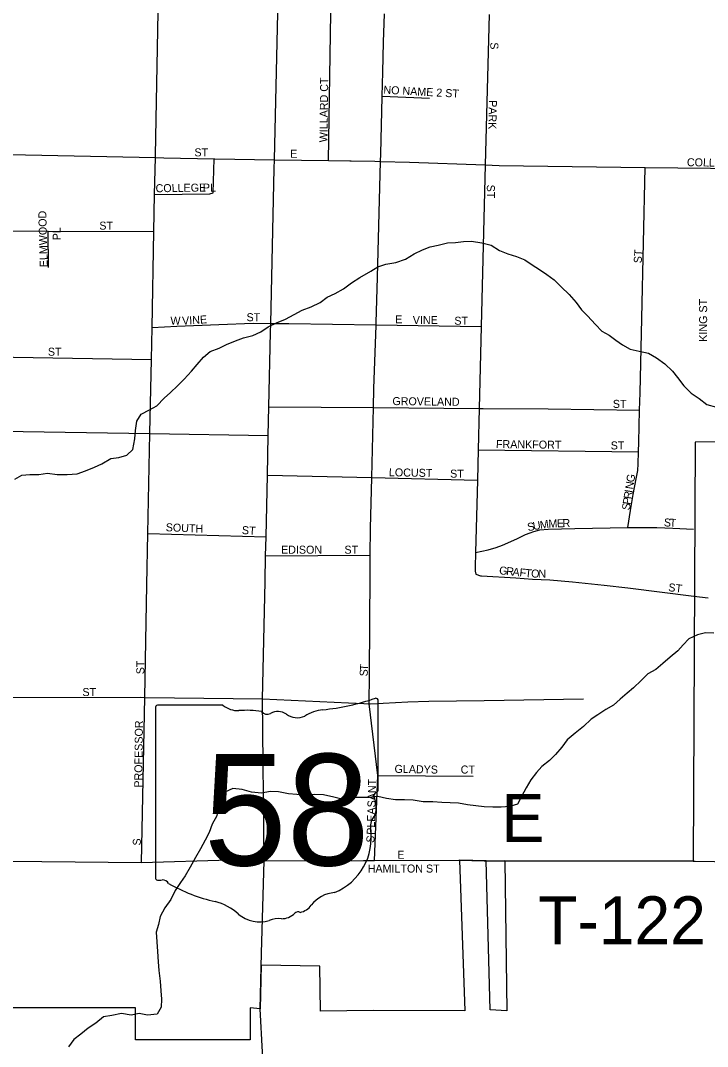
# Model space of a CAD drawing. Extents: x 1857828 to 2277390, y 930619 to 1324581.
# Drawn here: x 2044604 to 2048895, y 1193698 to 1200105 of the extents above; entities that cross this region are included whole.
import ezdxf

# ---------------------------------------------------------------- set-up
doc = ezdxf.new("R2010")
doc.units = 0
for name, color, linetype in [('GM_X_City_Street', 7, 'Continuous'), ('GM_X_City_Street_Text', 7, 'Continuous'), ('GM_X_Corporation', 7, 'Continuous'), ('GM_X_Minor_River', 7, 'Continuous'), ('GM_X_State_Location', 7, 'Continuous'), ('GM_X_State_Route', 7, 'Continuous'), ('GM_X_State_Shield', 7, 'Continuous'), ('GM_X_Township_Road', 7, 'Continuous'), ('GM_X_Township_Road_Text', 7, 'Continuous')]:
    doc.layers.add(name, color=color, linetype=linetype)

msp = doc.modelspace()

# ---------------------------------------------------------------- linework, layer by layer
at = {"layer": 'GM_X_City_Street'}
for points in [[(2045446.7, 1199263.6), (2045446.7, 1199263.6), (2045464.4, 1200157.6)], [(2046526.9, 1199230.2), (2046541.5, 1200150.6)], [(2046670.4, 1199228.3), (2046817, 1199226.3), (2046852.7, 1199225.3), (2047032.9, 1199220), (2047507, 1199203.7), (2047594.5, 1199200.7), (2048506.7, 1199187.8), (2048914.4, 1199183.5), (2049785.3, 1199177.2), (2050061.2, 1199175.5), (2050800.9, 1199205), (2050967.2, 1199208.4), (2051658.7, 1199196.2), (2051734, 1199217.2), (2052172.9, 1199504.5), (2052500.1, 1199734.7), (2053014.1, 1200096.5)], [(2046825.8, 1198209.1), (2046826.1, 1198216.6), (2046833.9, 1198503.3), (2046852.7, 1199225.3), (2046853.9, 1199273.1), (2046863.2, 1199628), (2046863.3, 1199632.7), (2046868, 1199782.4), (2046870.5, 1199970.8), (2046877.1, 1200147.7)], [(2047530.5, 1200142.3), (2047507, 1199203.7), (2047481.6, 1198193.5), (2047468.8, 1197682.7), (2047462.3, 1197423.5), (2047457.6, 1197235.2), (2047446.3, 1196783.5), (2047444, 1196692), (2047444.2, 1196666), (2047448.3, 1196648), (2047476.4, 1196638.2), (2047482.6, 1196637.8)], [(2046863.3, 1199632.7), (2047158.9, 1199620.1)], [(2044124.8, 1199276.8), (2045446.5, 1199249.9), (2045499.1, 1199248.8), (2045499.3, 1199248.8)], [(2045412.5, 1197528.1), (2045421.6, 1197989.2), (2045425.5, 1198188.6), (2045437.3, 1198787.4), (2045441.9, 1199018.2), (2045446.5, 1199249.9), (2045446.7, 1199263.6)], [(2045441.9, 1199018.2), (2045787.1, 1199022.8), (2045807, 1199029), (2045813, 1199242.4)], [(2045499.3, 1199248.8), (2045813, 1199242.4), (2045818.3, 1199242.3)], [(2045818.3, 1199242.3), (2046190.4, 1199234.7)], [(2046190.4, 1199234.7), (2046526.9, 1199230.2), (2046660.4, 1199228.4), (2046670.4, 1199228.3)], [(2048484.6, 1198244.1), (2048484.6, 1198245.5), (2048506.7, 1199187.8)], [(2043167.1, 1198799.5), (2043167.2, 1198799.5), (2043177.6, 1198799.3), (2044088.7, 1198791.9), (2044114.9, 1198791.9), (2044332.4, 1198791.7), (2044776.1, 1198790), (2045437.3, 1198787.4)], [(2044779.7, 1198562.5), (2044776.1, 1198790)], [(2048398.3, 1196938.6), (2048413.4, 1197045.5), (2048430.6, 1197145.8), (2048449.8, 1197242.2), (2048459.4, 1197294.4), (2048463.1, 1197336.5), (2048464.7, 1197412.6), (2048466, 1197472.8), (2048471, 1197671.2), (2048473.7, 1197779.6), (2048484.6, 1198244.1)], [(2045425.5, 1198188.6), (2045580.9, 1198195.9), (2045842.6, 1198206.1), (2046058.3, 1198215.9), (2046167.6, 1198212.3)], [(2046167.6, 1198212.3), (2046280.1, 1198213.7), (2046825.7, 1198204.5), (2047481.6, 1198193.5)], [(2046816.1, 1194858.7), (2046835.2, 1195391.2), (2046781.4, 1195837.6), (2046783, 1196021.3), (2046788.2, 1196648.8), (2046789, 1196767), (2046790, 1196933.4), (2046797.7, 1197250.6), (2046808.4, 1197688.1), (2046811.3, 1197807.5), (2046825.5, 1198200.8), (2046825.7, 1198204.5), (2046825.8, 1198209.1)], [(2043111.3, 1198029.2), (2044068.7, 1198012), (2044098.6, 1198011.5), (2044146.6, 1198010.6), (2044560.2, 1198003.6), (2045421.6, 1197989.2)], [(2046156, 1197693.4), (2046808.4, 1197688.1), (2047468.8, 1197682.7), (2047492.9, 1197682.5), (2047493.6, 1197682.5)], [(2047493.6, 1197682.5), (2047899.1, 1197679.2), (2048471, 1197671.2)], [(2043118.3, 1197563), (2044089.8, 1197547.3), (2045412.4, 1197526), (2046152, 1197514.1)], [(2045393.7, 1196581.5), (2045400, 1196901), (2045412.4, 1197526), (2045412.5, 1197528.1)], [(2047462.3, 1197423.5), (2048464.7, 1197412.6)], [(2046146.5, 1197265.7), (2046797.7, 1197250.6), (2047457.6, 1197235.2)], [(2045400, 1196901), (2046137.9, 1196880.3)], [(2047446.3, 1196783.5), (2047526.2, 1196800.5), (2047576.1, 1196814.9), (2047613.9, 1196829.2), (2047703.5, 1196867.9), (2047759.3, 1196896.4), (2047787.1, 1196906.6), (2047811, 1196914.8), (2047848.9, 1196925.1), (2047900.8, 1196929.5), (2048066.6, 1196932.7), (2048398.3, 1196938.6), (2048446.1, 1196939.5), (2048578, 1196938.4), (2048677.9, 1196935.2), (2048807.8, 1196928.1)], [(2046135.2, 1196762.1), (2046789, 1196767)], [(2047482.6, 1196637.8), (2047698.3, 1196624), (2047802.3, 1196616.8), (2047910.2, 1196611.7), (2048052.2, 1196598.9), (2048250.2, 1196578.4), (2048398.2, 1196561.6), (2048810.8, 1196511.1), (2048899.6, 1196500)], [(2045359.4, 1194846.1), (2045379.8, 1195878.3), (2045393.7, 1196581.5), (2045393.7, 1196581.5)], [(2042662.4, 1194873.5), (2042664.6, 1195109.3), (2042671.2, 1195279.7), (2042676.5, 1195380), (2042684.2, 1195410.1), (2042696, 1195434.3), (2042721.9, 1195454.5), (2042763.7, 1195468.8), (2043876.1, 1195779.6), (2044093.4, 1195839.3), (2044145.3, 1195853.7), (2044189.1, 1195864.1), (2044247, 1195872.5), (2044300.9, 1195876.9), (2044356.8, 1195877.3), (2044490.7, 1195878.3), (2045355.7, 1195878.6), (2045379.4, 1195878.3)], [(2045379.4, 1195878.3), (2045379.8, 1195878.3), (2045381.9, 1195878.3), (2046115.3, 1195869.5)], [(2046115.3, 1195869.5), (2046652.6, 1195844), (2046748.5, 1195840.7), (2046781.4, 1195837.6), (2046788.5, 1195836.9), (2046834.5, 1195839.5), (2046834.8, 1195839.5)], [(2046834.8, 1195839.5), (2046870.3, 1195841.5), (2047024.1, 1195850.7), (2047153.9, 1195853.6), (2047499.5, 1195858.2), (2048120.7, 1195868.7)], [(2046835.2, 1195391.2), (2047431.2, 1195386.6)], [(2041697.8, 1194883.4), (2041706.6, 1194883.3), (2042662.4, 1194873.5), (2045359.4, 1194846.1), (2045912.2, 1194863.5), (2046030.1, 1194860), (2046066.8, 1194858.9)], [(2046066.8, 1194858.9), (2046125.8, 1194857.1)], [(2046125.8, 1194857.1), (2046747.5, 1194858.6), (2046792.2, 1194858.7), (2046816.1, 1194858.7), (2047342.9, 1194862.3)], [(2047500.9, 1194857.9), (2047513.1, 1194857.5), (2047606.2, 1194856.7)]]:
    msp.add_lwpolyline(points, dxfattribs=at)
at = {"layer": 'GM_X_Corporation'}
msp.add_lwpolyline([(2051694.1, 1197494.8), (2048818.4, 1197472.4), (2048806.7, 1194856.2), (2047629.8, 1194856.4), (2047642.2, 1193919.8), (2047537.4, 1193926.2), (2047513.1, 1194857.5), (2047346, 1194862.3), (2047379.1, 1193919.8), (2046807.5, 1193921.8), (2046477.5, 1193918.9), (2046474.2, 1194200.3), (2046107.4, 1194206.5), (2046100.3, 1193934.1), (2046037.6, 1193939.9), (2046037.6, 1193739.8), (2045321.5, 1193739.9), (2045321.5, 1193940), (2042130.6, 1193940.3), (2042130.5, 1193127.5)], dxfattribs=at)
at = {"layer": 'GM_X_Minor_River'}
for points in [[(2046835.8, 1198566.9), (2046885.8, 1198583), (2046947.7, 1198593.1), (2047009.7, 1198615.3), (2047063.6, 1198647.4), (2047115.6, 1198673.6), (2047163.5, 1198691.7), (2047213.5, 1198701.8), (2047271.5, 1198715.9), (2047321.5, 1198718), (2047371.5, 1198726.1), (2047421.5, 1198728.1), (2047485.5, 1198716.2), (2047543.6, 1198702.2), (2047595.6, 1198668.2), (2047647.7, 1198648.3), (2047701.7, 1198632.3), (2047753.8, 1198610.3), (2047799.9, 1198580.3), (2047845.9, 1198550.3), (2047892, 1198518.3), (2047938.1, 1198486.3), (2047982.2, 1198442.3), (2048030.3, 1198394.2), (2048074.4, 1198344.2), (2048108.6, 1198298.1), (2048146.7, 1198260.1), (2048194.8, 1198206), (2048234.9, 1198166), (2048280.9, 1198140), (2048323, 1198109.9), (2048365.1, 1198079.9), (2048413.2, 1198051.9), (2048469.2, 1198040), (2048527.2, 1198028.1), (2048577.3, 1197998), (2048629.4, 1197962), (2048677.5, 1197916), (2048707.6, 1197875.9), (2048747.7, 1197823.9), (2048793.8, 1197777.8), (2048843.9, 1197743.8), (2048892, 1197707.8), (2048952.1, 1197689.8)], [(2044568.7, 1197240.5), (2044612.6, 1197266.7), (2044662.6, 1197270.7), (2044718.6, 1197270.8), (2044772.6, 1197278.9), (2044832.6, 1197271), (2044894.6, 1197269.1), (2044958.6, 1197275.2), (2045010.6, 1197293.3), (2045066.5, 1197315.4), (2045112.5, 1197337.5), (2045168.4, 1197369.7), (2045218.4, 1197375.8), (2045268.4, 1197389.9), (2045306.3, 1197426), (2045318.2, 1197492.2), (2045322, 1197544.3), (2045329.9, 1197602.5), (2045357.8, 1197646.6), (2045409.7, 1197674.8), (2045455.7, 1197698.9), (2045501.6, 1197747.1), (2045541.5, 1197783.2), (2045585.4, 1197823.4), (2045627.3, 1197865.5), (2045671.2, 1197915.7), (2045707.1, 1197957.9), (2045747, 1198002), (2045788.9, 1198038.2), (2045844.9, 1198058.3), (2045890.8, 1198082.4), (2045946.8, 1198104.6), (2045996.8, 1198122.7), (2046054.7, 1198138.8), (2046104.7, 1198160.9), (2046150.6, 1198193.1), (2046202.6, 1198217.2), (2046258.5, 1198239.3), (2046314.4, 1198269.5), (2046364.4, 1198295.6), (2046420.3, 1198317.7), (2046476.3, 1198343.9), (2046520.2, 1198378), (2046570.2, 1198400.1), (2046622.1, 1198430.3), (2046672, 1198466.4), (2046723.9, 1198500.6), (2046791.9, 1198540.8), (2046835.8, 1198566.9)], [(2048935.4, 1196278.5), (2048883.4, 1196280.4), (2048833.4, 1196268.3), (2048779.4, 1196244.2), (2048743.5, 1196206), (2048709.6, 1196167.9), (2048661.7, 1196129.7), (2048615.8, 1196089.6), (2048571.9, 1196051.4), (2048521.9, 1196025.3), (2048482, 1195983.1), (2048434.1, 1195936.9), (2048394.2, 1195904.8), (2048350.3, 1195866.6), (2048308.3, 1195830.5), (2048260.4, 1195802.4), (2048210.5, 1195770.2), (2048168.5, 1195742.1), (2048120.7, 1195695.9), (2048068.7, 1195655.7), (2048018.8, 1195613.6), (2047984.9, 1195567.4), (2047945, 1195521.2), (2047909.1, 1195483.1), (2047861.2, 1195446.9), (2047827.3, 1195408.8), (2047791.4, 1195362.6), (2047763.5, 1195312.5), (2047733.6, 1195258.3), (2047707.7, 1195212.2), (2047659.8, 1195196.1), (2047605.8, 1195192), (2047553.8, 1195191.9), (2047499.8, 1195193.8), (2047447.7, 1195201.8), (2047395.7, 1195207.7), (2047339.7, 1195217.6), (2047287.7, 1195219.6)], [(2047287.7, 1195219.6), (2047235.7, 1195221.5), (2047179.7, 1195225.4), (2047119.6, 1195225.4), (2047057.6, 1195235.3), (2047003.6, 1195239.2), (2046945.6, 1195239.1), (2046889.6, 1195247.1), (2046835.5, 1195259), (2046779.5, 1195252.9), (2046723.5, 1195252.9), (2046669.5, 1195252.8), (2046619.6, 1195240.7), (2046561.5, 1195254.6), (2046497.5, 1195268.6), (2046441.5, 1195272.5), (2046389.5, 1195270.4), (2046329.5, 1195272.3), (2046277.4, 1195276.3), (2046215.4, 1195288.2), (2046163.4, 1195290.1), (2046109.4, 1195280), (2046047.4, 1195286), (2045989.3, 1195303.9), (2045929.3, 1195309.9), (2045879.4, 1195285.7), (2045855.5, 1195241.6), (2045839.6, 1195191.4), (2045829.7, 1195139.3), (2045801.8, 1195087.1), (2045782, 1195035), (2045758.1, 1194986.8), (2045728.2, 1194932.7), (2045696.3, 1194878.5), (2045664.4, 1194818.3), (2045632.6, 1194764.1), (2045602.7, 1194722), (2045570.8, 1194671.8), (2045542.9, 1194615.6), (2045505, 1194563.5), (2045477.1, 1194509.3), (2045465.3, 1194459.2), (2045451.4, 1194411), (2045455.5, 1194350.9), (2045459.7, 1194290.8), (2045463.8, 1194226.6), (2045467.9, 1194172.5), (2045476.1, 1194106.3), (2045480.2, 1194046.2), (2045484.3, 1193994.1), (2045482.5, 1193944), (2045458.6, 1193899.8), (2045396.6, 1193893.7), (2045344.5, 1193903.7), (2045294.6, 1193893.6), (2045234.5, 1193903.5), (2045174.6, 1193891.4), (2045122.6, 1193883.3), (2045074.7, 1193843.1), (2045026.7, 1193813), (2044980.8, 1193774.8), (2044936.9, 1193740.7), (2044903, 1193696.5)]]:
    msp.add_lwpolyline(points, dxfattribs=at)
at = {"layer": 'GM_X_State_Route'}
for points in [[(2046189.2, 1199180.9), (2046190.4, 1199234.7), (2046210.9, 1200153.3)], [(2046166.4, 1198158.6), (2046167.6, 1198212.3), (2046189.2, 1199180.9)], [(2046131.6, 1196599.6), (2046131.7, 1196601.4), (2046135.2, 1196762.1), (2046137.9, 1196880.3), (2046146.5, 1197265.7), (2046152, 1197514.1), (2046156, 1197693.4), (2046166.4, 1198158.6)], [(2046125.8, 1194857.1), (2046115.3, 1195869.5), (2046131.6, 1196599.6)], [(2046109.9, 1194281.7), (2046125.8, 1194857.1)], [(2046224.7, 1192985.3), (2046210.8, 1193045.7), (2046206.9, 1193062.9), (2046130.5, 1193392), (2046100.3, 1193934.1), (2046109.9, 1194281.7)]]:
    msp.add_lwpolyline(points, dxfattribs=at)
at = {"layer": 'GM_X_State_Shield'}
for p, q in [((2045446.6, 1195810.8), (2045446.6, 1194754.2)), ((2045868, 1195829), (2045460.3, 1195829)), ((2046838.7, 1195302.4), (2046838.7, 1195855.2)), ((2046838.6, 1195302.6), (2046838.7, 1195302.4))]:
    msp.add_line(p, q, dxfattribs=at)
for centre, radius, start, end in [((2046342.8, 1197269.5), 1476.4, 275.84447, 288.90645), ((2046823.3, 1195857.5), 15.5, 351.86209, 97.738), ((2045462.5, 1195813.1), 16.1, 98.1301, 188.1301), ((2045965.1, 1195951.7), 156.4, 231.61951, 271.11188), ((2046531.1, 1195506.3), 297, 97.34618, 120.76885), ((2046016.9, 1195235.8), 561.6, 80.48669, 94.98827), ((2046144.4, 1195818.5), 45.1, 219.79206, 297.10237), ((2046210.7, 1195696.4), 93.8, 54.46668, 119.14113), ((2046331.8, 1195863.9), 112.9, 233.85621, 294.82819), ((2046822.2, 1195300.3), 16.6, 289.60381, 7.73413), ((2046835.2, 1195261.9), 24, 107.94398, 210.33697), ((2046682.6, 1195192), 144, 340.03296, 23.64957), ((2046894.3, 1195071.1), 104.8, 136.8065, 186.92959), ((2046425.5, 1195000.8), 369.3, 292.30889, 8.98584), ((2045462.7, 1194751.9), 16.3, 171.95839, 258.30661), ((2045465.1, 1194860), 124.2, 267.33899, 280.60386), ((2045490.5, 1194693.2), 44.8, 29.74838, 93.27175), ((2046055.8, 1195642.6), 1066.1, 240.41292, 257.1985), ((2046581.2, 1194457.5), 202.2, 94.40312, 142.57675), ((2045738, 1194279.5), 333.6, 47.18416, 75.83597), ((2046098.7, 1194688), 211.7, 230.70037, 286.29184), ((2046236.5, 1194608.8), 112.8, 268.77702, 315.54927), ((2046338.5, 1194506.5), 31.8, 65.75173, 132.64842), ((2046325, 1194651.8), 119.3, 282.87319, 323.27711), ((2046221, 1194322.6), 173.9, 85.69512, 111.20995)]:
    msp.add_arc(centre, radius, start, end, dxfattribs=at)
at = {"layer": 'GM_X_Township_Road'}
for points in [[(2047342.9, 1194862.3), (2047345.9, 1194862.3), (2047500.9, 1194857.9)], [(2047606.2, 1194856.7), (2047629.8, 1194856.4), (2048806.7, 1194856.2), (2048818, 1194856)], [(2048818, 1194856), (2052062.8, 1194799.2), (2053528.4, 1194778.3), (2053769.6, 1194772.9)]]:
    msp.add_lwpolyline(points, dxfattribs=at)

# ---------------------------------------------------------------- texts
at = {"layer": 'GM_X_City_Street_Text'}
for s, rotation, p in [('S', 270, (2047538.9, 1199969.2)), ('WILLARD CT', 89.32632, (2046521.3, 1199344.5)), ('NO NAME 2 ST', 356.95682, (2046870.1, 1199648.6)), ('PARK', 268.78171, (2047530.2, 1199608.2)), ('ST', 0.00001, (2045690.3, 1199257)), ('E', 0.00001, (2046288.8, 1199248.2)), ('COLLEGE', 359.21694, (2048766.4, 1199195.4)), ('COLLEGE', 0.90888, (2045448.2, 1199032.6)), ('PL', 0.00001, (2045743.2, 1199037)), ('ST', 270, (2047517, 1199080.4)), ('ELMWOOD', 91.59325, (2044774.5, 1198565.3)), ('PL', 90, (2044855.2, 1198732.8)), ('ST', 0.00001, (2045096.4, 1198799.4)), ('ST', 86.42535, (2048483.8, 1198588.2)), ('KING ST', 90, (2048892.9, 1198099.2)), ('W', 0.00001, (2045540.7, 1198205.4)), ('VINE', 3.46623, (2045615, 1198205.4)), ('ST', 0.00001, (2046016, 1198227.4)), ('E', 0.00001, (2046944.3, 1198214.2)), ('VINE', 0.00001, (2047054.4, 1198209.8)), ('ST', 0.00001, (2047313.9, 1198205.4)), ('ST', 0.00001, (2044775.1, 1198011.8)), ('GROVELAND', 359.33416, (2046926.9, 1197703.8)), ('ST', 0.00001, (2048304, 1197686.2)), ('FRANKFORT', 359.3101, (2047573.7, 1197435.4)), ('ST', 0.00001, (2048290.7, 1197426.6)), ('LOCUST', 358.93969, (2046904.9, 1197259.4)), ('ST', 0.00001, (2047287.5, 1197250.6)), ('N', 81.1142, (2048429.5, 1197175)), ('G', 80.22501, (2048436.2, 1197218.3)), ('R', 81.10059, (2048419.9, 1197114.2)), ('I', 81.09099, (2048426.1, 1197153.3)), ('S', 81.11259, (2048409.1, 1197044.6)), ('P', 81.11259, (2048414.5, 1197079.4)), ('SOUTH', 357.51189, (2045510.4, 1196916.2)), ('S', 10.02381, (2047774.3, 1196916.1)), ('U', 10.03885, (2047808.9, 1196922.2)), ('M', 8.55508, (2047851.9, 1196929.8)), ('M', 2.67866, (2047902.8, 1196937.5)), ('E', 1.77626, (2047955.3, 1196940)), ('R', 1.78682, (2047990.5, 1196941.1)), ('S', 355.84432, (2048621.5, 1196947)), ('T', 357.289, (2048658, 1196944.3)), ('ST', 356.42537, (2045985.7, 1196898.6)), ('EDISON', 0.00001, (2046231.6, 1196775.4)), ('ST', 0.00001, (2046627.6, 1196775.4)), ('G', 354.08936, (2047592.1, 1196647.7)), ('R', 354.08886, (2047635.9, 1196643.2)), ('A', 354.10102, (2047675.3, 1196639.1)), ('F', 354.08824, (2047719.1, 1196634.6)), ('T', 354.34993, (2047754.3, 1196631)), ('O', 358.13503, (2047793, 1196627.3)), ('N', 359.97035, (2047838.7, 1196625.8)), ('ST', 352.8649, (2048648.3, 1196542.1)), ('ST', 90, (2045377.3, 1196022.4)), ('T', 86.08958, (2046773.7, 1196043.5)), ('S', 87.37634, (2046772.1, 1196008.6)), ('ST', 0.00001, (2044990.7, 1195886.6)), ('PROFESSOR', 89.34927, (2045364.1, 1195314.1)), ('GLADYS', 358.97753, (2046940.1, 1195407)), ('CT', 0.00001, (2047353.6, 1195402.6)), ('PLEASANT', 88.38424, (2046816.1, 1195019.5)), ('S', 90, (2045355.4, 1194953.2)), ('S', 82.8817, (2046811.8, 1194967.5)), ('E', 0.00001, (2046957.6, 1194870.2)), ('HAMILTON ST', 0.00001, (2046772.8, 1194784.2))]:
    msp.add_text(s, height=50, rotation=rotation, dxfattribs=at).set_placement(p)
at = {"layer": 'GM_X_State_Location'}
for s in ['s', 'r']:
    msp.add_text(s, height=1, dxfattribs=at).set_placement((2046127, 1195212.2))
msp.add_text('58', height=1, rotation=0.00001, dxfattribs=at).set_placement((2045875.1, 1195139.5))
at = {"layer": 'GM_X_State_Shield'}
msp.add_text('58', height=696.1, dxfattribs=at).set_placement((2045749.1, 1194828.7))
at = {"layer": 'GM_X_Township_Road_Text'}
for s, p in [('E', (2047608.7, 1194974.3)), ('T-122', (2047837.5, 1194335.7))]:
    msp.add_text(s, height=300, rotation=0.00001, dxfattribs=at).set_placement(p)

doc.saveas('drawing.dxf')
